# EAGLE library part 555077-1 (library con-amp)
AMP connector
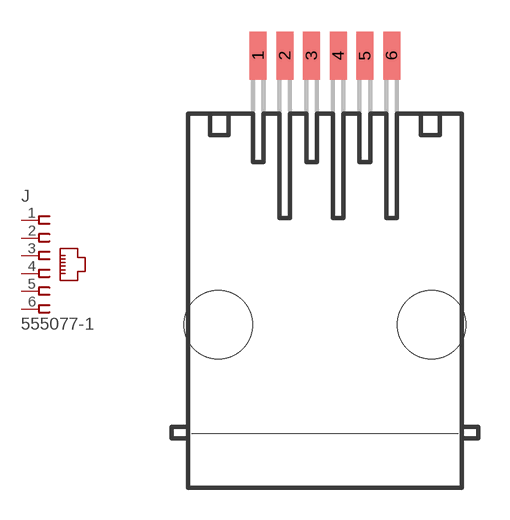
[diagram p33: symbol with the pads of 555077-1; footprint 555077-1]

Designator prefix J

## 555077-1 (MF: TYCO ELECTRONICS; MPN: 5555077-1; OC_FARNELL: unknown; OC_NEWARK: 42K8745)  [555077-1]
1  1  pas
2  2  pas
3  3  pas
4  4  pas
5  5  pas
6  6  pas

## Footprint 555077-1 (pad centres in mm)
Modular Jack with Panel Stops
smd 0.813 x 2.286: 1 -3.175,12.803; 2 -1.905,12.803; 3 -0.635,12.803; 4 0.635,12.803; 5 1.905,12.803; 6 3.175,12.803
hole 3.251 at -5.08,0
hole 3.251 at 5.08,0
